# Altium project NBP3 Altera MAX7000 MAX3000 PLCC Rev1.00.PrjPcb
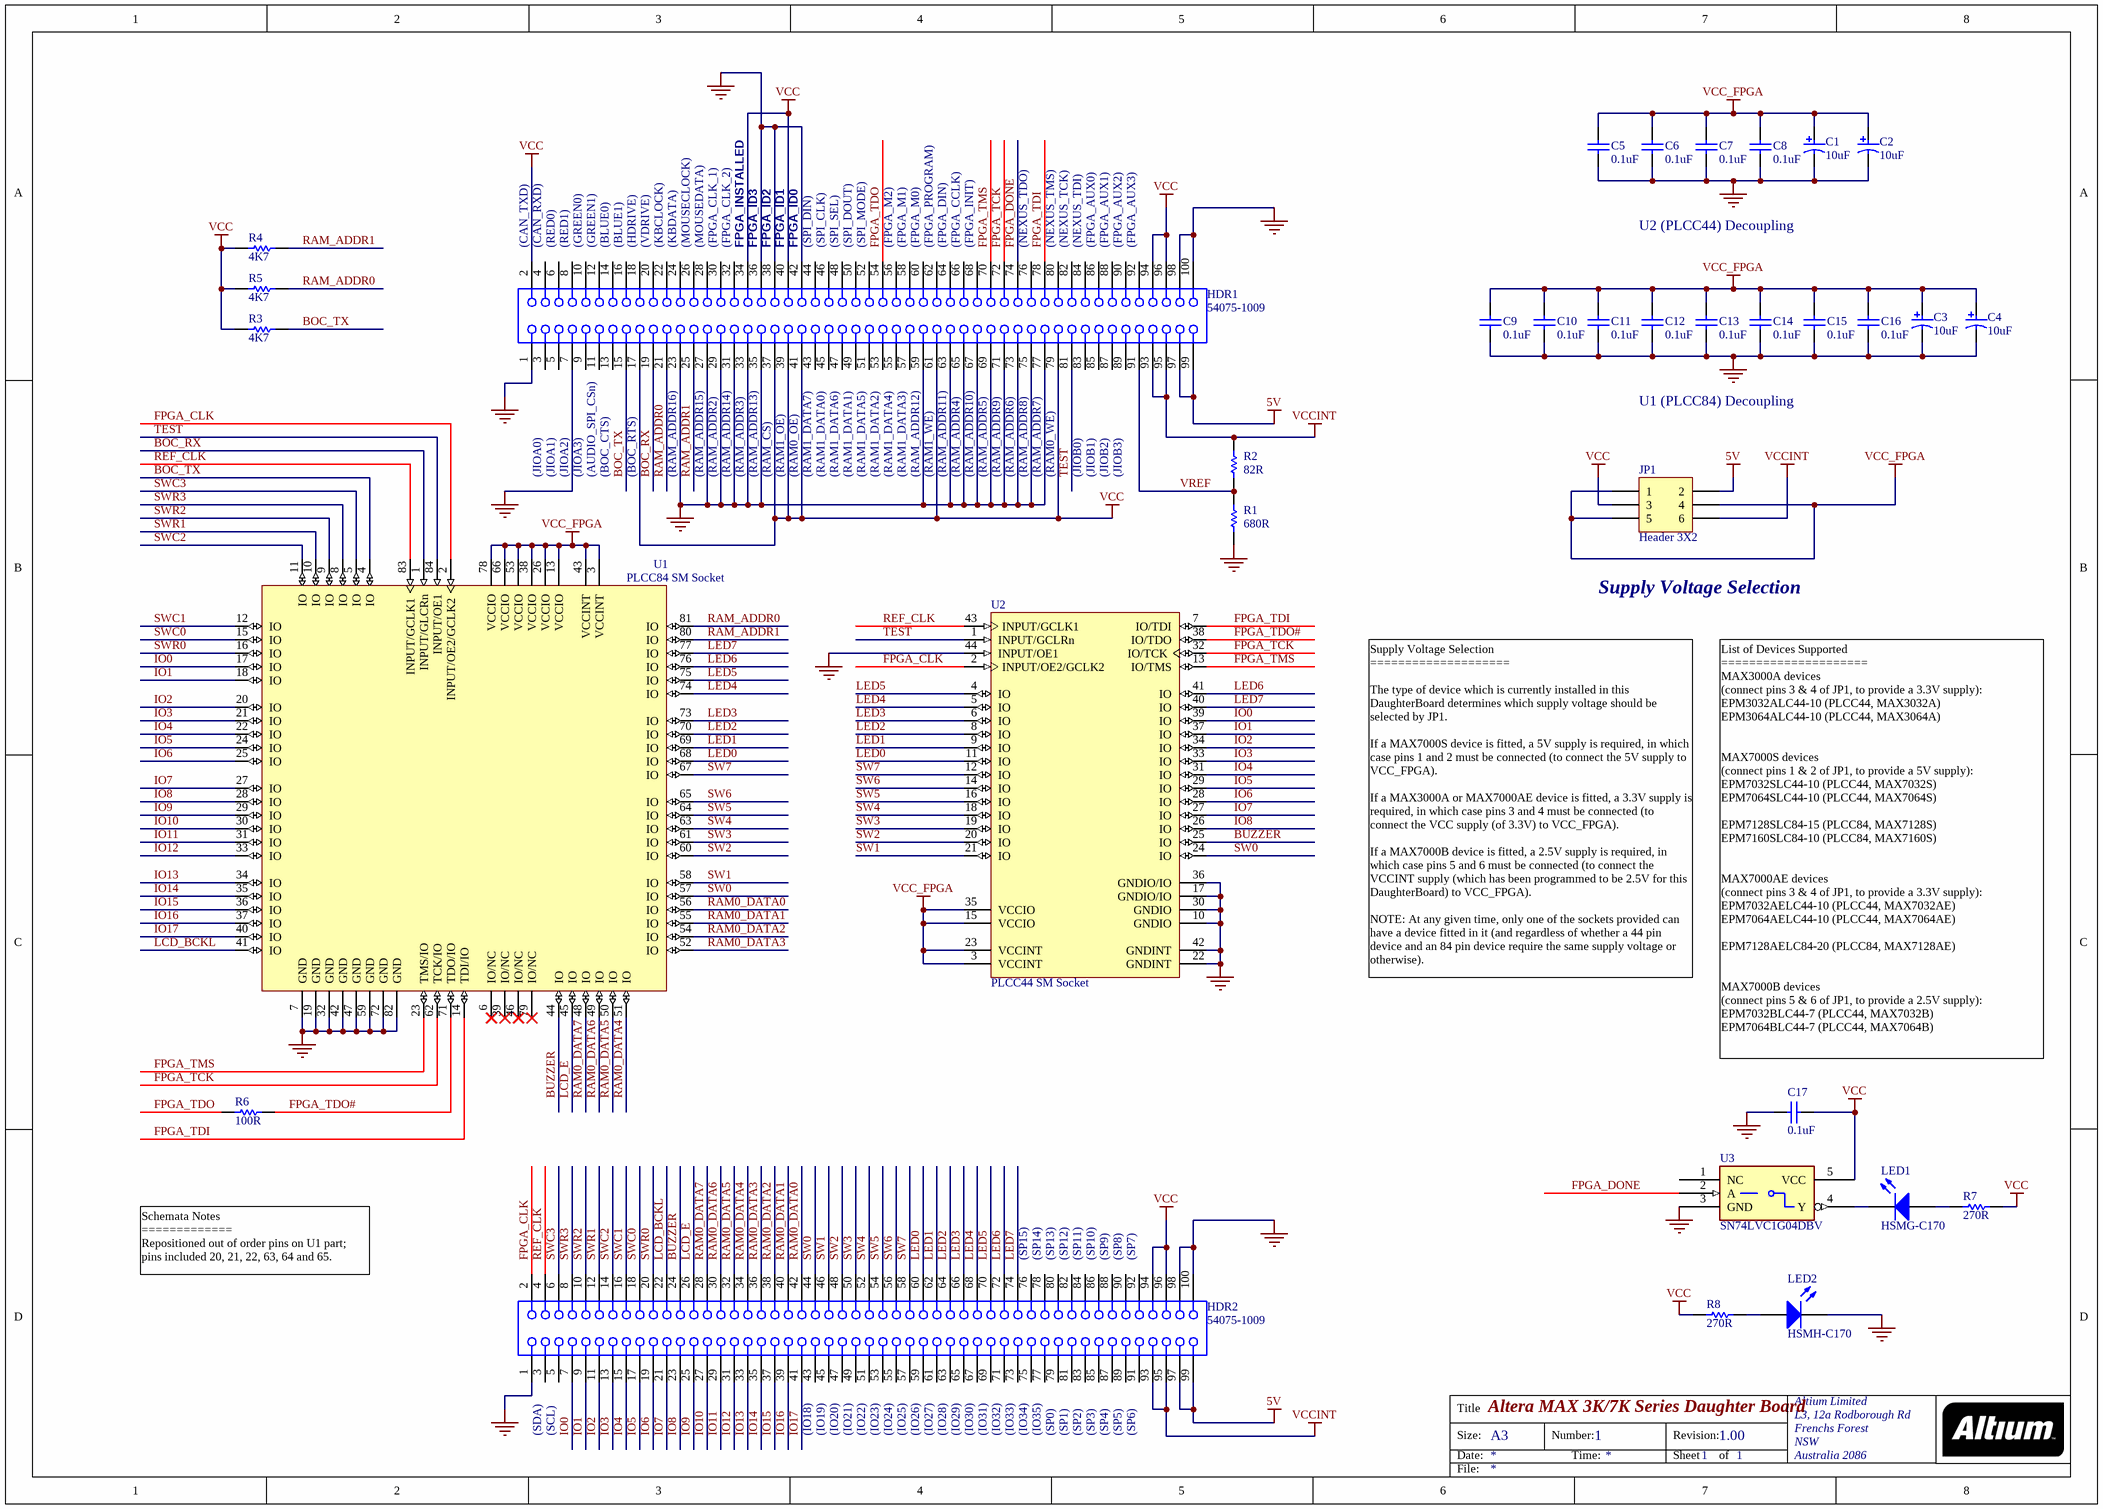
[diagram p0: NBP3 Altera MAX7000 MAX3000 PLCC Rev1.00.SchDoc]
1 sheet, 33 parts. Net scope: global (net labels, ports and power ports of the same name join across sheets).
Board file: NBP3 Altera MAX7000 MAX3000 PLCC Rev1.00.PcbDoc

## Sheet NBP3 Altera MAX7000 MAX3000 PLCC Rev1.00.SchDoc: Altera MAX 3K/7K Series Daughter Board
size A3; Organization: Altium Limited; Address1: L3, 12a Rodborough Rd; Address2: Frenchs Forest; Address3: NSW; Address4: Australia 2086; DocumentNumber: 1; Revision: 1.00; SheetNumber: 1; SheetTotal: 1

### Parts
C1  10uF  [MCCT-B]
C2  10uF  [MCCT-B]
C3  10uF  [MCCT-B]
C4  10uF  [MCCT-B]
C5  0.1uF  [CC2012-0805]
C6  0.1uF  [CC2012-0805]
C7  0.1uF  [CC2012-0805]
C8  0.1uF  [CC2012-0805]
C9  0.1uF  [CC2012-0805]
C10  0.1uF  [CC2012-0805]
C11  0.1uF  [CC2012-0805]
C12  0.1uF  [CC2012-0805]
C13  0.1uF  [CC2012-0805]
C14  0.1uF  [CC2012-0805]
C15  0.1uF  [CC2012-0805]
C16  0.1uF  [CC2012-0805]
C17  0.1uF  [CC2012-0805]
HDR1  54075-1009  [54075]
HDR2  54075-1009  [54075]
JP1  Header 3X2  [HDR2X3]
LED1  HSMG-C170  [SMD _LED]
LED2  HSMH-C170  [SMD _LED]
R1  680R  [CC2012-0805]
R2  82R  [CC2012-0805]
R3  4K7  [CC2012-0805]
R4  4K7  [CC2012-0805]
R5  4K7  [CC2012-0805]
R6  100R  [CC2012-0805]
R7  270R  [CC2012-0805]
R8  270R  [CC2012-0805]
U1  PLCC84 SM Socket  [PLCC84_SKT_SM]
U2  PLCC44 SM Socket  [PLCC44_SKT_SM]
U3  SN74LVC1G04DBV  [SO-G5/P.95]

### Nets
5V: HDR1.97 HDR1.99 HDR2.97 HDR2.99 JP1.2
GND: C1.2 C2.2 C3.2 C4.2 C5.2 C6.2 C7.2 C8.2 C9.1 C10.1 C11.1 C12.2 C13.1 C14.2 C15.2 C16.2 C17.2 HDR1.1 HDR1.7 HDR1.23 HDR1.27 HDR1.29 HDR1.31 HDR1.33 HDR1.35 HDR1.36 HDR1.38 HDR1.42 HDR1.59 HDR1.63 HDR1.65 HDR1.67 HDR1.69 HDR1.71 HDR1.73 HDR1.75 HDR1.77 HDR1.98 HDR1.100 HDR2.1 HDR2.98 HDR2.100 LED2.2(K) R1.2 U1.7(GND) U1.19(GND) U1.32(GND) U1.42(GND) U1.47(GND) U1.59(GND) U1.72(GND) U1.82(GND) U2.10(GNDIO) U2.17(GNDIO/IO) U2.22(GNDINT) U2.30(GNDIO) U2.36(GNDIO/IO) U2.42(GNDINT) U2.44(INPUT/OE1) U3.3(GND)
VCC: C17.1 HDR1.2 HDR1.17 HDR1.34 HDR1.37 HDR1.39 HDR1.40 HDR1.41 HDR1.61 HDR1.79 HDR1.94 HDR1.96 HDR2.94 HDR2.96 JP1.3 R3.1 R4.1 R5.1 R7.1 R8.1 U3.5(VCC)
VCC_FPGA: C1.1 C2.1 C3.1 C4.1 C5.1 C6.1 C7.1 C8.1 C9.2 C10.2 C11.2 C12.1 C13.2 C14.1 C15.1 C16.1 JP1.1 JP1.4 JP1.5 U1.3(VCCINT) U1.13(VCCIO) U1.26(VCCIO) U1.38(VCCIO) U1.43(VCCINT) U1.53(VCCIO) U1.66(VCCIO) U1.78(VCCIO) U2.3(VCCINT) U2.15(VCCIO) U2.23(VCCINT) U2.35(VCCIO)
VCCINT: HDR1.93 HDR1.95 HDR2.93 HDR2.95 JP1.6 R2.1
BOC_RX: HDR1.19 U1.1(INPUT/GLCRn)
BOC_TX: HDR1.15 R3.2 U1.4(IO)
BUZZER: HDR2.24 U1.44(IO) U2.25(IO)
FPGA_CLK: HDR2.2 U1.2(INPUT/OE2/GCLK2) U2.2(INPUT/OE2/GCLK2)
FPGA_DONE: HDR1.74 U3.2(A)
FPGA_TCK: HDR1.72 U1.62(TCK/IO) U2.32(IO/TCK)
FPGA_TDI: HDR1.78 U1.14(TDI/IO) U2.7(IO/TDI)
FPGA_TDO: HDR1.54 R6.1
FPGA_TDO#: R6.2 U1.71(TDO/IO) U2.38(IO/TDO)
FPGA_TMS: HDR1.70 U1.23(TMS/IO) U2.13(IO/TMS)
IO0: HDR2.7 U1.17(IO) U2.39(IO)
IO1: HDR2.9 U1.18(IO) U2.37(IO)
IO2: HDR2.11 U1.20(IO) U2.34(IO)
IO3: HDR2.13 U1.21(IO) U2.33(IO)
IO4: HDR2.15 U1.22(IO) U2.31(IO)
IO5: HDR2.17 U1.24(IO) U2.29(IO)
IO6: HDR2.19 U1.25(IO) U2.28(IO)
IO7: HDR2.21 U1.27(IO) U2.27(IO)
IO8: HDR2.23 U1.28(IO) U2.26(IO)
IO9: HDR2.25 U1.29(IO)
IO10: HDR2.27 U1.30(IO)
IO11: HDR2.29 U1.31(IO)
IO12: HDR2.31 U1.33(IO)
IO13: HDR2.33 U1.34(IO)
IO14: HDR2.35 U1.35(IO)
IO15: HDR2.37 U1.36(IO)
IO16: HDR2.39 U1.37(IO)
IO17: HDR2.41 U1.40(IO)
LCD_BCKL: HDR2.22 U1.41(IO)
LCD_E: HDR2.26 U1.45(IO)
LED0: HDR2.60 U1.68(IO) U2.11(IO)
LED1: HDR2.62 U1.69(IO) U2.9(IO)
LED2: HDR2.64 U1.70(IO) U2.8(IO)
LED3: HDR2.66 U1.73(IO) U2.6(IO)
LED4: HDR2.68 U1.74(IO) U2.5(IO)
LED5: HDR2.70 U1.75(IO) U2.4(IO)
LED6: HDR2.72 U1.76(IO) U2.41(IO)
LED7: HDR2.74 U1.77(IO) U2.40(IO)
RAM0_DATA0: HDR2.42 U1.56(IO)
RAM0_DATA1: HDR2.40 U1.55(IO)
RAM0_DATA2: HDR2.38 U1.54(IO)
RAM0_DATA3: HDR2.36 U1.52(IO)
RAM0_DATA4: HDR2.34 U1.51(IO)
RAM0_DATA5: HDR2.32 U1.50(IO)
RAM0_DATA6: HDR2.30 U1.49(IO)
RAM0_DATA7: HDR2.28 U1.48(IO)
RAM_ADDR0: HDR1.21 R5.2 U1.81(IO)
RAM_ADDR1: HDR1.25 R4.2 U1.80(IO)
REF_CLK: HDR2.4 U1.83(INPUT/GCLK1) U2.43(INPUT/GCLK1)
SW0: HDR2.44 U1.57(IO) U2.24(IO)
SW1: HDR2.46 U1.58(IO) U2.21(IO)
SW2: HDR2.48 U1.60(IO) U2.20(IO)
SW3: HDR2.50 U1.61(IO) U2.19(IO)
SW4: HDR2.52 U1.63(IO) U2.18(IO)
SW5: HDR2.54 U1.64(IO) U2.16(IO)
SW6: HDR2.56 U1.65(IO) U2.14(IO)
SW7: HDR2.58 U1.67(IO) U2.12(IO)
SWC0: HDR2.18 U1.15(IO)
SWC1: HDR2.16 U1.12(IO)
SWC2: HDR2.14 U1.11(IO)
SWC3: HDR2.6 U1.5(IO)
SWR0: HDR2.20 U1.16(IO)
SWR1: HDR2.12 U1.10(IO)
SWR2: HDR2.10 U1.9(IO)
SWR3: HDR2.8 U1.8(IO)
TEST: HDR1.81 U1.84(INPUT/OE1) U2.1(INPUT/GCLRn)
VREF: HDR1.91 R1.1 R2.2
NetLED1_1: LED1.1(A) R7.2
NetLED1_2: LED1.2(K) U3.4(Y)
NetLED2_1: LED2.1(A) R8.2

Not connected (* = marked no-connect by the designer): HDR1 3 4 5 6 8 9 10 11 12 13 14 16 18 20 22 24 26 28 30 32 43 44 45 46 47 48 49 50 51 52 53 55 56 57 58 60 62 64 66 68 76 80 82 83 84 85 86 87 88 89 90 92; HDR2 3 5 43 45 47 49 51 53 55 57 59 61 63 65 67 69 71 73 75 76 77 78 79 80 81 82 83 84 85 86 87 88 89 90 91 92; U1 6(IO/NC)* 39(IO/NC)* 46(IO/NC)* 79(IO/NC)*; U3 1(NC)

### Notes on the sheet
- (near HDR1) (CAN_TXD)
- (near HDR1) (CAN_RXD)
- (near HDR1) (RED0)
- (near HDR1) (RED1)
- (near HDR1) (GREEN0)
- (near HDR1) (GREEN1)
- (near HDR1) (BLUE0)
- (near HDR1) (BLUE1)
- (near HDR1) (HDRIVE)
- (near HDR1) (VDRIVE)
- (near HDR1) (KBCLOCK)
- (near HDR1) (KBDATA)
- (near HDR1) (MOUSECLOCK)
- (near HDR1) (MOUSEDATA)
- (near HDR1) (FPGA_CLK_1)
- (near HDR1) (FPGA_CLK_2)
- (near HDR1) FPGA_INSTALLED
- (near HDR1) FPGA_ID3
- (near HDR1) FPGA_ID2
- (near HDR1) FPGA_ID1
- (near HDR1) FPGA_ID0
- (near HDR1) (SPI_DIN)
- (near HDR1) (SPI_CLK)
- (near HDR1) (SPI_SEL)
- (near HDR1) (SPI_DOUT)
- (near HDR1) (SPI_MODE)
- (near HDR1) (FPGA_M2)
- (near HDR1) (FPGA_M1)
- (near HDR1) (FPGA_M0)
- (near HDR1) (FPGA_PROGRAM)
- (near HDR1) (FPGA_DIN)
- (near HDR1) (FPGA_CCLK)
- (near HDR1) (FPGA_INIT)
- (near HDR1) (NEXUS_TDO)
- (near HDR1) (NEXUS_TMS)
- (near HDR1) (NEXUS_TCK)
- (near HDR1) (NEXUS_TDI)
- (near HDR1) (FPGA_AUX0)
- (near HDR1) (FPGA_AUX1)
- (near HDR1) (FPGA_AUX2)
- (near HDR1) (FPGA_AUX3)
- U2 (PLCC44) Decoupling
- U1 (PLCC84) Decoupling
- (JIOA0)
- (JIOA1)
- (JIOA2)
- (JIOA3)
- (near HDR1) (AUDIO_SPI_CSn)
- (BOC_CTS)
- (BOC_RTS)
- (RAM_ADDR16)
- (RAM_ADDR15)
- (RAM_ADDR2)
- (RAM_ADDR14)
- (RAM_ADDR3)
- (RAM_ADDR13)
- (RAM_CS)
- (RAM1_OE)
- (RAM0_OE)
- (RAM1_DATA7)
- (RAM1_DATA0)
- (RAM1_DATA6)
- (RAM1_DATA1)
- (RAM1_DATA5)
- (RAM1_DATA2)
- (RAM1_DATA4)
- (RAM1_DATA3)
- (RAM_ADDR12)
- (RAM1_WE)
- (RAM_ADDR11)
- (RAM_ADDR4)
- (RAM_ADDR10)
- (RAM_ADDR5)
- (RAM_ADDR9)
- (RAM_ADDR6)
- (RAM_ADDR8)
- (RAM_ADDR7)
- (RAM0_WE)
- (JIOB0)
- (JIOB1)
- (JIOB2)
- (JIOB3)
- Supply Voltage Selection
- Supply Voltage Selection
  ====================
  The type of device which is currently installed in this DaughterBoard determines which supply voltage should be selected by JP1.
  If a MAX7000S device is fitted, a 5V supply is required, in which case pins 1 and 2 must be connected (to connect the 5V supply to VCC_FPGA).
  If a MAX3000A or MAX7000AE device is fitted, a 3.3V supply is required, in which case pins 3 and 4 must be connected (to connect the VCC supply (of 3.3V) to VCC_FPGA).
  If a MAX7000B device is fitted, a 2.5V supply is required, in which case pins 5 and 6 must be connected (to connect the VCCINT supply (which has been programmed to be 2.5V for this DaughterBoard) to VCC_FPGA).
  NOTE: At any given time, only one of the sockets provided can have a device fitted in it (and regardless of whether a 44 pin device and an 84 pin device require the same supply voltage or otherwise).
- List of Devices Supported
  =====================
  MAX3000A devices
  (connect pins 3 & 4 of JP1, to provide a 3.3V supply):
  EPM3032ALC44-10 (PLCC44, MAX3032A)
  EPM3064ALC44-10 (PLCC44, MAX3064A)
  MAX7000S devices
  (connect pins 1 & 2 of JP1, to provide a 5V supply):
  EPM7032SLC44-10 (PLCC44, MAX7032S)
  EPM7064SLC44-10 (PLCC44, MAX7064S)
  EPM7128SLC84-15 (PLCC84, MAX7128S)
  EPM7160SLC84-10 (PLCC84, MAX7160S)
  MAX7000AE devices
  (connect pins 3 & 4 of JP1, to provide a 3.3V supply):
  EPM7032AELC44-10 (PLCC44, MAX7032AE)
  EPM7064AELC44-10 (PLCC44, MAX7064AE)
  EPM7128AELC84-20 (PLCC84, MAX7128AE)
  MAX7000B devices
  (connect pins 5 & 6 of JP1, to provide a 2.5V supply):
  EPM7032BLC44-7 (PLCC44, MAX7032B)
  EPM7064BLC44-7 (PLCC44, MAX7064B)
- (near HDR2) (SP15)
- (near HDR2) (SP14)
- (near HDR2) (SP13)
- (near HDR2) (SP12)
- (near HDR2) (SP11)
- (near HDR2) (SP10)
- (near HDR2) (SP9)
- (near HDR2) (SP8)
- (near HDR2) (SP7)
- Schemata Notes
  =============
  Repositioned out of order pins on U1 part;
  pins included 20, 21, 22, 63, 64 and 65.
- (near HDR2) (SDA)
- (near HDR2) (SCL)
- (near HDR2) (IO18)
- (near HDR2) (IO19)
- (near HDR2) (IO20)
- (near HDR2) (IO21)
- (near HDR2) (IO22)
- (near HDR2) (IO23)
- (near HDR2) (IO24)
- (near HDR2) (IO25)
- (near HDR2) (IO26)
- (near HDR2) (IO27)
- (near HDR2) (IO28)
- (near HDR2) (IO29)
- (near HDR2) (IO30)
- (near HDR2) (IO31)
- (near HDR2) (IO32)
- (near HDR2) (IO33)
- (near HDR2) (IO34)
- (near HDR2) (IO35)
- (near HDR2) (SP0)
- (near HDR2) (SP1)
- (near HDR2) (SP2)
- (near HDR2) (SP3)
- (near HDR2) (SP4)
- (near HDR2) (SP5)
- (near HDR2) (SP6)

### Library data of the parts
C1-C4 = CAP_POLAR: Polar Capacitor
C5-C17 = CAP: Capacitor
HDR1 HDR2 = 54075-1009: Board-to-Board, Docking Station, 0.80mm (.031") Pitch, Shielded Receptacle, Vertical, Ultra Low Profile, SMT; Manufacturer: Molex; Package Information: Latest Revision: Jun-2001; Mating Height: 8.5mm; Voltage: 100V; Current: 0.5A; Contact Resistance: 40mOhm max; PCB Layout: Complies with Manufacturer's Recommendation.
JP1 = Header 3X2: Header, 3-Pin, Dual row
LED1 LED2 = HSMX-C670: Typical RED GaAs SMD LED Agilent make; Manufacturer: Generic Components; Class I: Optoelectronic; Fitted: True
R1-R8 = RES: Resistor
U1 = EPM7160SLC84-10: MAX 7000S 5V In-System Programmable CPLD, 160 Macrocells, 84-Pin PLCC, Speed Grade 10, Commercial Grade; Package Information: Latest Revision: ver11.0, Feb-2003; Code - JEDEC: MS-018-AF; Code - IPC: PLCC-84
U2 = EPM3032ALC44-10: MAX 3032, 44-Pin PLCC, Speed Grade 10, Commercial Grade; Package Information: Latest Revision: ver11.0, Feb-2003; Code - IPC: PLCC-44
U3 = SN74AHC1G04DBVR: Manufacturer: TI; Fitted: True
